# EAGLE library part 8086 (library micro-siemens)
MICROPROCESSOR/PERIPHERAL DEVICE
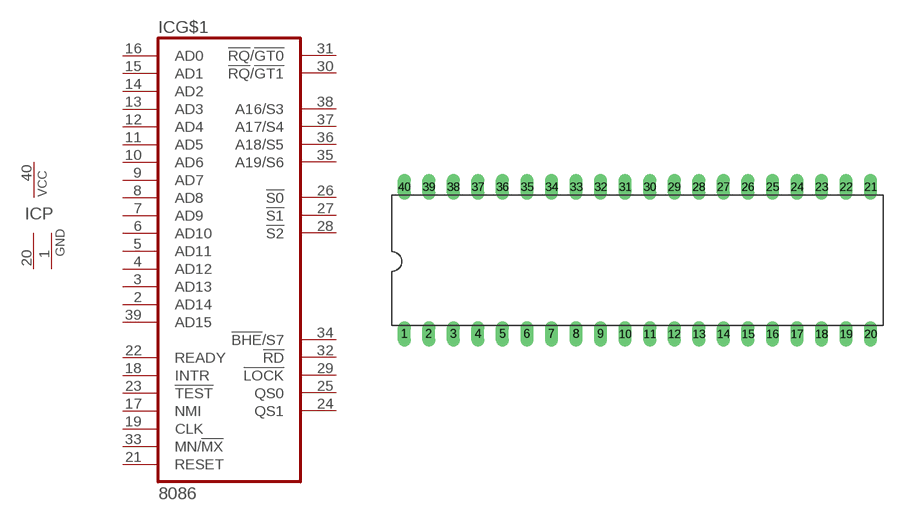
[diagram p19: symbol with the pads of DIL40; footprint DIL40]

Designator prefix IC; gates G$1=8086 P=1VCC2GND

## 8086 (OC_FARNELL: unknown; OC_NEWARK: unknown)  [DIL40]
1  P:GND  pwr
2  G$1:AD14
3  G$1:AD13
4  G$1:AD12
5  G$1:AD11
6  G$1:AD10
7  G$1:AD9
8  G$1:AD8
9  G$1:AD7
10  G$1:AD6
11  G$1:AD5
12  G$1:AD4
13  G$1:AD3
14  G$1:AD2
15  G$1:AD1
16  G$1:AD0
17  G$1:NMI  in
18  G$1:INTR  in
19  G$1:CLK  in
20  P:GND  pwr
21  G$1:RESET  in
22  G$1:READY  in
23  G$1:!TEST  in
24  G$1:QS1  out
25  G$1:QS0  out
26  G$1:!S0  out
27  G$1:!S1  out
28  G$1:!S2  out
29  G$1:!LOCK  out
30  G$1:!RQ!/!GT1
31  G$1:!RQ!/!GT0
32  G$1:!RD  out
33  G$1:MN/!MX  in
34  G$1:!BHE!/S7  out
35  G$1:A19/S6  out
36  G$1:A18/S5  out
37  G$1:A17/S4  out
38  G$1:A16/S3  out
39  G$1:AD15
40  P:VCC  pwr

## Footprint DIL40 (pad centres in mm)
Dual In Line Package
drill 0.813 long: 1 -24.13,-7.62; 2 -21.59,-7.62; 3 -19.05,-7.62; 4 -16.51,-7.62; 5 -13.97,-7.62; 6 -11.43,-7.62; 7 -8.89,-7.62; 8 -6.35,-7.62; 9 -3.81,-7.62; 10 -1.27,-7.62; 11 1.27,-7.62; 12 3.81,-7.62; 13 6.35,-7.62; 14 8.89,-7.62; 15 11.43,-7.62; 16 13.97,-7.62; 17 16.51,-7.62; 18 19.05,-7.62; 19 21.59,-7.62; 20 24.13,-7.62; 21 24.13,7.62; 22 21.59,7.62; 23 19.05,7.62; 24 16.51,7.62; 25 13.97,7.62; 26 11.43,7.62; 27 8.89,7.62; 28 6.35,7.62; 29 3.81,7.62; 30 1.27,7.62; 31 -1.27,7.62; 32 -3.81,7.62; 33 -6.35,7.62; 34 -8.89,7.62; 35 -11.43,7.62; 36 -13.97,7.62; 37 -16.51,7.62; 38 -19.05,7.62; 39 -21.59,7.62; 40 -24.13,7.62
